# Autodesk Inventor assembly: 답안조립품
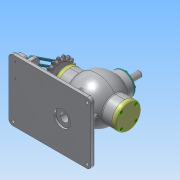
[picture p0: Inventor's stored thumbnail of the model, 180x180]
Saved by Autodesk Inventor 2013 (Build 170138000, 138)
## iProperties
Created: 2017-07
Part Number: 답안조립품
Document SubType Name: Assembly
Designer: Administrator
Mass: 3277.44 g
Surface Area: 2432.27 cm^2
Volume: 944.508 cm^3
Density: 3.47 g/cm^3
Author: Administrator
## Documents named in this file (20)
- C:\Users\Administrator\Desktop\370708V1022\답안조립품.iam
- C:\Users\Administrator\Desktop\370708V1022\본체.ipt
- C:\Users\Administrator\Desktop\370708V1022\고정핀.ipt
- C:\Users\Administrator\Desktop\370708V1022\너트 M8x1.ipt
- C:\Users\Administrator\Desktop\370708V1022\둥근머리 볼트 M4x8.ipt
- C:\Users\Administrator\Desktop\370708V1022\뒤커버.ipt
- C:\Users\Administrator\Desktop\370708V1022\베어링 6202.ipt
- C:\Users\Administrator\Desktop\370708V1022\본체커버.ipt
- C:\Users\Administrator\Desktop\370708V1022\볼트 M4x12.ipt
- C:\Users\Administrator\Desktop\370708V1022\스프로킷.ipt
- C:\Users\Administrator\Desktop\370708V1022\스프링.ipt
- C:\Users\Administrator\Desktop\370708V1022\슬라이드 커버.ipt
- C:\Users\Administrator\Desktop\370708V1022\슬라이드.ipt
- C:\Users\Administrator\Desktop\370708V1022\앞커버.ipt
- C:\Users\Administrator\Desktop\370708V1022\연결대.ipt
- C:\Users\Administrator\Desktop\370708V1022\오일실.ipt
- C:\Users\Administrator\Desktop\370708V1022\와셔 8x17.ipt
- C:\Users\Administrator\Desktop\370708V1022\와셔 ISO 7093 A.ipt
- C:\Users\Administrator\Desktop\370708V1022\축.ipt
- C:\Users\Administrator\Desktop\370708V1022\키 3 x 3 x 12.ipt
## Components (1 placed, 1 different names)
1. 고정핀:1
